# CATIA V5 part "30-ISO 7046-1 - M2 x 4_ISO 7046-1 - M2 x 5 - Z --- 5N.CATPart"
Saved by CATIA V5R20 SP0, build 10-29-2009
Part number: 30-ISO 7046-1 - M2 x 4_ISO 7046-1 - M2 x 5 - Z --- 5N
Revision: ANY
Definition: UNKNOWN
Nomenclature: 30-ISO 7046-1 - M2 x 4_ISO 7046-1 - M2 x 5 - Z --- 5N
Source: Unknown
Bounding box of the stored display mesh (mm): x 0 to 4, y -1.9 to 1.9, z -1.9 to 1.9
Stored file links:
  C:\Users\Utente\Desktop\IO LAVORO\3D X SITO CF\CUMSA\3D files CC\CCHS5328\30-ISO 7046-1 - M2 x 4_ISO 7046-1 - M2 x 5 - Z --- 5N.CATPart
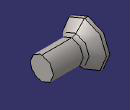
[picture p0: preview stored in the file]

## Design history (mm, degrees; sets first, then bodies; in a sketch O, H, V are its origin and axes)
Body1 "RecessCore" (main body)
  Solid1: solid without history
